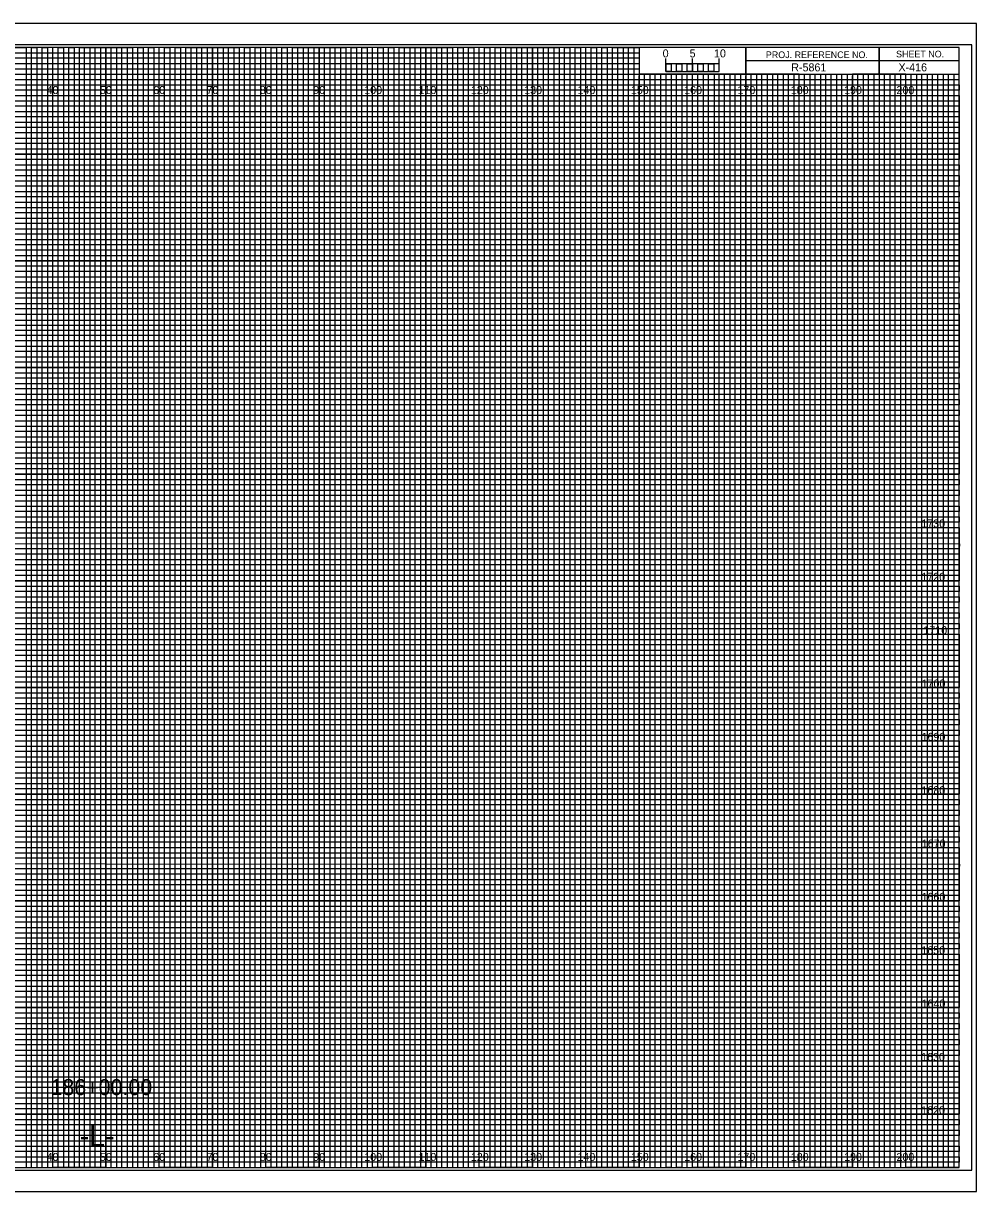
# Model space of a CAD drawing. Extents: x -13 to 323, y -5 to 6154.
# Drawn here: x 144.5 to 323.3, y 2635.5 to 2854.5 of the extents above; entities that cross this region are included whole.
import ezdxf

# ---------------------------------------------------------------- set-up
doc = ezdxf.new("R2010")
doc.units = 0
for name, color, linetype in [('Exist CMT Ground Line', 7, 'Continuous'), ('Prop Horizontal Alignment', 7, 'Continuous'), ('Prop Retaining Wall', 7, 'Continuous'), ('Prop XS Alignment Label', 7, 'Continuous'), ('Prop XS Bar Scale Labels', 7, 'Continuous'), ('Prop XS DDE', 7, 'Continuous'), ('Prop XS DDE Elevations', 7, 'Continuous'), ('Prop XS DDE Slope Text', 7, 'Continuous'), ('Prop XS Earthwork Shape', 7, 'Continuous'), ('Prop XS Elevation Labels', 7, 'Continuous'), ('Prop XS Project Number', 7, 'Continuous'), ('Prop XS Sheet Number', 7, 'Continuous'), ('Prop XS Station Labels', 7, 'Continuous'), ('Raster_Level_0', 7, 'Continuous'), ('Scratch_Level_3', 7, 'Continuous'), ('Sheet Cutting Line CELL', 7, 'Continuous')]:
    doc.layers.add(name, color=color, linetype=linetype)

msp = doc.modelspace()

# ---------------------------------------------------------------- linework, layer by layer
at = {"layer": 'Exist CMT Ground Line'}
for p, q in [((265, 2845.49), (265, 2847.9)), ((265, 2846.9), (265, 2847.9)), ((270, 2845.49), (270, 2847.9)), ((275, 2845.49), (275, 2847.9)), ((275, 2846.9), (275, 2847.9))]:
    msp.add_line(p, q, dxfattribs=at)
for points in [[(275, 2846.9), (265, 2846.9), (265, 2845.49), (275, 2845.49)], [(265, 2846.9), (266, 2846.9), (266, 2845.49), (265, 2845.49)], [(267, 2846.9), (268, 2846.9), (268, 2845.49), (267, 2845.49)], [(269, 2846.9), (270, 2846.9), (270, 2845.49), (269, 2845.49)], [(271, 2846.9), (272, 2846.9), (272, 2845.49), (271, 2845.49)], [(273, 2846.9), (274, 2846.9), (274, 2845.49), (273, 2845.49)]]:
    msp.add_lwpolyline(points, close=True, dxfattribs=at)
at = {"layer": 'Prop Retaining Wall'}
for p, q in [((0, 2849), (260, 2849)), ((260, 2847.98), (0, 2847.98)), ((0, 2847), (260, 2847)), ((260, 2849), (260, 2847.98)), ((260, 2847), (260, 2845.89)), ((260, 2845.89), (0, 2845.89)), ((0, 2844), (320, 2844))]:
    msp.add_line(p, q, dxfattribs=at)
for points in [[(0, 2843), (270, 2843), (320, 2843), (320, 2842), (0, 2842)], [(0, 2841), (320, 2841), (320, 2839), (0, 2839)], [(0, 2838), (320, 2838), (320, 2837), (0, 2836.98)], [(0, 2836), (320, 2836), (320, 2834), (0, 2834)], [(0, 2833), (320, 2833), (320, 2832), (0, 2832)], [(0, 2831), (320, 2831), (320, 2829), (0, 2829)], [(0, 2828), (320, 2828), (320, 2827), (0, 2827)], [(0, 2826), (320, 2826), (320, 2824), (0, 2824)], [(0, 2823), (320, 2823), (320, 2822), (0, 2822)], [(0, 2821), (320, 2821), (320, 2819), (0, 2819)], [(0, 2818), (320, 2818), (320, 2817), (0, 2817)], [(0, 2816), (320, 2816), (320, 2813.95), (320, 2813), (320, 2812), (0, 2812)], [(0, 2814), (320, 2814), (320, 2813), (0, 2813)], [(0, 2811), (320, 2811), (320, 2809), (0, 2809.03)], [(0, 2809.03), (320, 2809), (320, 2808), (0, 2808)], [(0, 2807), (320, 2807), (320, 2806), (0, 2806)], [(0, 2804), (320, 2804), (320, 2803), (0, 2803)], [(0, 2802), (320, 2802), (320, 2801), (0, 2801)], [(-0.07, 2798.89), (320, 2798.89), (320, 2797.88), (-0.07, 2797.88)], [(0, 2797), (320, 2797), (320, 2796), (0, 2796)], [(0, 2794), (320, 2794), (320, 2793), (0, 2793)], [(0, 2792), (320, 2792), (320, 2791), (0, 2791)], [(0, 2789), (320, 2789), (320, 2788), (0, 2788)], [(0, 2787), (320, 2787), (320, 2786), (0, 2786)], [(0, 2784), (320, 2784), (320, 2783), (0, 2783)], [(0, 2782), (320, 2782), (320, 2781), (0, 2781)], [(0, 2779), (320, 2779), (319.99, 2777.98), (0, 2778)], [(0, 2777), (320, 2777), (320, 2776), (0, 2776)], [(0, 2774), (320, 2774), (320, 2773), (0, 2773)], [(0, 2772), (320, 2772), (320, 2771), (0, 2771)], [(0, 2769), (320, 2769), (320, 2768), (0, 2768)], [(0, 2767), (320, 2767), (320, 2766), (0, 2766)], [(0, 2764), (320, 2764), (320, 2763), (0, 2763)], [(0, 2762), (320, 2762), (320, 2761), (0, 2761)], [(0, 2759), (320, 2759), (320, 2758), (0, 2758)], [(0, 2756.99), (320.07, 2756.91), (320, 2756), (0, 2756)], [(0, 2754), (320, 2754), (320, 2753), (0, 2753)], [(0, 2752), (320, 2752), (320, 2751), (0, 2751)], [(0, 2749), (320, 2749), (320, 2748), (0, 2748)], [(0, 2747), (320, 2747), (320, 2746), (0, 2746)], [(0, 2744), (320, 2744), (320, 2743), (0, 2743)], [(0, 2742), (320, 2742), (320, 2741), (0, 2741)], [(0, 2739), (320, 2739), (320, 2738), (0, 2738)], [(0, 2737), (320, 2737), (320, 2736), (0, 2736)], [(0, 2734), (320, 2734), (320, 2733), (0, 2733)], [(0, 2732), (320, 2732), (320, 2731), (0, 2731)], [(0, 2729), (320, 2729), (320, 2728), (0, 2728)], [(0, 2727), (320, 2727), (320, 2726), (0, 2726)], [(0, 2724), (320, 2724), (320, 2723), (0, 2723)], [(0, 2722), (320, 2722), (320, 2721), (0, 2721)], [(0, 2719), (320, 2719), (319.99, 2717.98), (0, 2718)], [(0, 2717), (320, 2717), (320, 2716), (0, 2716)], [(0, 2714), (320, 2714), (320, 2713), (0, 2713)], [(0, 2712), (320, 2712), (320, 2711), (0, 2711)], [(0, 2709), (320, 2709), (320, 2708), (0, 2708)], [(0, 2707), (320, 2707), (320, 2706), (0, 2706)], [(0, 2704), (320, 2704), (320, 2703), (0, 2703)], [(0, 2702), (320, 2702), (320, 2701), (0, 2701)], [(0, 2699), (320, 2699), (320, 2698), (0, 2698)], [(0, 2696.99), (320.07, 2696.91), (320, 2696), (0, 2696)], [(0, 2694), (320, 2694), (320, 2693), (0, 2693)], [(0, 2692), (320, 2692), (320, 2691), (0, 2691)], [(0, 2689), (320, 2689), (320, 2688), (0, 2688)], [(0, 2687), (320, 2687), (320, 2686), (0, 2686)], [(0, 2684), (320, 2684), (320, 2683), (0, 2683)], [(0, 2682), (320, 2682), (320, 2681), (0, 2681)], [(0, 2679), (320, 2679), (320, 2678), (0, 2678)], [(0, 2677), (320, 2677), (320, 2676), (0, 2676)], [(0, 2674), (320, 2674), (320, 2673), (0, 2673)], [(0, 2672), (320, 2672), (320, 2671), (0, 2671)], [(0, 2669), (320, 2669), (320, 2668), (0, 2668)], [(0, 2667), (320, 2667), (320, 2666), (0, 2666)], [(0, 2664), (320, 2664), (320, 2663), (0, 2663)], [(0, 2662), (320, 2662), (320, 2661), (0, 2661)], [(0, 2659), (320, 2659), (320, 2658), (0, 2658)], [(0, 2657), (320, 2657), (320, 2656), (0, 2656)], [(0, 2654), (320, 2654), (320, 2653), (0, 2653)], [(0, 2652), (320, 2652), (320, 2651), (0, 2651)], [(0, 2649), (320, 2649), (320, 2648), (0, 2648)], [(0, 2647), (320, 2647), (320, 2646), (0, 2646)], [(0, 2644), (320, 2644), (320, 2643), (0, 2643)], [(0, 2642), (320, 2642), (320, 2641), (0, 2641)]]:
    msp.add_lwpolyline(points, dxfattribs=at)
at = {"layer": 'Prop XS Alignment Label'}
for p, q in [((305, 2850), (305, 2845)), ((305, 2845), (305, 2850)), ((280, 2847.5), (280, 2845)), ((320, 2847.49), (280, 2847.49)), ((280, 2845), (320, 2845))]:
    msp.add_line(p, q, dxfattribs=at)
for points in [[(320, 2850), (0, 2850), (0, 2640), (320, 2640)], [(280, 2850), (260, 2850), (260, 2845.03), (280, 2845.03)], [(320, 2850), (280, 2850), (280, 2845), (320, 2845)]]:
    msp.add_lwpolyline(points, close=True, dxfattribs=at)
at = {"layer": 'Prop XS DDE'}
msp.add_lwpolyline([(-13.4, 2635.5), (323.3, 2635.5), (323.3, 2854.5), (-13.4, 2854.5)], close=True, dxfattribs=at)
at = {"layer": 'Prop XS DDE Elevations'}
for p, q in [((150, 2640), (150, 2850)), ((160, 2640), (160, 2850)), ((170, 2640), (170, 2850)), ((180, 2640), (180, 2850)), ((190, 2640), (190, 2850)), ((200, 2640), (200, 2850)), ((210, 2640), (210, 2850)), ((220, 2640), (220, 2850)), ((230, 2640), (230, 2850)), ((240, 2640), (240, 2850)), ((250, 2640), (250, 2850)), ((260, 2640), (260, 2844.69)), ((270, 2640), (270, 2844.69)), ((280, 2640), (280, 2844.69)), ((290, 2640), (290, 2844.69)), ((300, 2640), (300, 2844.69)), ((310, 2640), (310, 2844.69)), ((0, 2840), (320, 2840)), ((0, 2830), (320, 2830)), ((0, 2820), (320, 2820)), ((0, 2810), (320, 2810)), ((0, 2800), (320, 2800)), ((0, 2790), (320, 2790)), ((0, 2780), (320, 2780)), ((0, 2770), (320, 2770)), ((0, 2760), (320, 2760)), ((0, 2750), (320, 2750)), ((0, 2740), (320, 2740)), ((0, 2730), (320, 2730)), ((0, 2720), (320, 2720)), ((0, 2710), (320, 2710)), ((0, 2700), (320, 2700)), ((0, 2690), (320, 2690)), ((0, 2680), (320, 2680)), ((0, 2670), (320, 2670)), ((0, 2660), (320, 2660)), ((0, 2650), (320, 2650))]:
    msp.add_line(p, q, dxfattribs=at)
at = {"layer": 'Prop XS DDE Slope Text'}
msp.add_lwpolyline([(-10.8, 2639.5), (322.4, 2639.5), (322.4, 2850.5), (-10.8, 2850.5)], close=True, dxfattribs=at)
at = {"layer": 'Prop XS Earthwork Shape'}
for p, q in [((150, 2850), (140, 2850)), ((150, 2640), (150, 2850)), ((170, 2850), (160, 2850)), ((160, 2850), (160, 2640)), ((170, 2640), (170, 2850)), ((190, 2850), (180, 2850)), ((180, 2850), (180, 2640)), ((190, 2640), (190, 2850)), ((210, 2850), (200, 2850)), ((200, 2850), (200, 2640)), ((210, 2640), (210, 2850)), ((230, 2850), (220, 2850)), ((220, 2850), (220, 2640)), ((230, 2640), (230, 2850)), ((250, 2850), (240, 2850)), ((240, 2850), (240, 2640)), ((250, 2640), (250, 2850)), ((260, 2850), (260, 2640)), ((270, 2640), (270, 2845)), ((290, 2845), (280, 2845)), ((280, 2845), (280, 2640)), ((290, 2640), (290, 2845)), ((310, 2845), (300, 2845)), ((300, 2845), (300, 2640)), ((310, 2640), (310, 2845)), ((160, 2640), (150, 2640)), ((180, 2640), (170, 2640)), ((200, 2640), (190, 2640)), ((220, 2640), (210, 2640)), ((240, 2640), (230, 2640)), ((260, 2640), (250, 2640)), ((280, 2640), (270, 2640)), ((300, 2640), (290, 2640)), ((320, 2640), (310, 2640)), ((320, 2640), (320, 2640))]:
    msp.add_line(p, q, dxfattribs=at)
for points in [[(0, 2840), (320, 2840), (320, 2830), (0, 2830)], [(0, 2820), (320, 2820), (320, 2810), (0, 2810)], [(0, 2800), (320, 2800), (320, 2790), (0, 2790)], [(0, 2780), (320, 2780), (320, 2770), (0, 2770)], [(0, 2760), (320, 2760), (320, 2750), (0, 2750)], [(0, 2740), (320, 2740), (320, 2730), (0, 2730)], [(0, 2720), (320, 2720), (320, 2710), (0, 2710)], [(0, 2700), (320, 2700), (320, 2690), (0, 2690)], [(0, 2680), (320, 2680), (320, 2670), (0, 2670)], [(0, 2660), (320, 2660), (320, 2650), (0, 2650)]]:
    msp.add_lwpolyline(points, dxfattribs=at)
at = {"layer": 'Prop XS Elevation Labels'}
for p, q in [((267, 2845), (266.01, 2845)), ((266.01, 2845), (266.01, 2640)), ((267, 2640), (267, 2845)), ((269, 2845), (268, 2845)), ((268, 2845), (268, 2640)), ((269, 2640), (269, 2845)), ((266.01, 2640), (265, 2640)), ((268, 2640), (267, 2640))]:
    msp.add_line(p, q, dxfattribs=at)
for points in [[(145, 2640), (146, 2640), (146, 2850), (147, 2850), (147, 2640)], [(147, 2640), (148, 2640), (148, 2850), (149, 2850), (149, 2640)], [(150, 2640), (151, 2640), (151, 2850), (152, 2850), (152, 2640)], [(152, 2640), (153, 2640), (153, 2850), (154, 2850), (154, 2640)], [(155, 2640), (156, 2640), (156, 2850), (157, 2850), (157, 2640)], [(157, 2640), (158, 2640), (158, 2850), (159, 2850), (159, 2640)], [(160, 2640), (161, 2640), (161, 2850), (162, 2850), (162, 2640)], [(162, 2640), (163, 2640), (163, 2850), (164, 2850), (164, 2640)], [(165, 2640), (166, 2640), (166, 2850), (167, 2850), (167, 2640)], [(167, 2640), (168, 2640), (168, 2850), (169, 2850), (169, 2640)], [(170, 2640), (171, 2640), (171, 2850), (172, 2850), (172, 2640)], [(172, 2640), (173, 2640), (173, 2850), (174, 2850), (174, 2640)], [(175, 2640), (176, 2640), (176, 2850), (177, 2850), (177, 2640)], [(177, 2640), (178, 2640), (178, 2850), (179, 2850), (179, 2640)], [(180, 2640), (181, 2640), (181, 2850), (182, 2850), (182, 2640)], [(182, 2640), (183, 2640), (183, 2850), (184, 2850), (184, 2640)], [(185, 2640), (186, 2640), (186, 2850), (187, 2850), (187, 2640)], [(187, 2640), (188, 2640), (188, 2850), (189, 2850), (189, 2640)], [(190, 2640), (191, 2640), (191, 2850), (192, 2850), (192, 2640)], [(192, 2640), (193, 2640), (193, 2850), (194, 2850), (194, 2640)], [(195, 2640), (196, 2640), (196, 2850), (197, 2850), (197, 2640)], [(197, 2640), (198, 2640), (198, 2850), (199, 2850), (199, 2640)], [(200, 2640), (201, 2640), (201, 2850), (202, 2850), (202, 2640)], [(202, 2640), (203, 2640), (203, 2850), (204, 2850), (204, 2640)], [(205, 2640), (206, 2640), (206, 2850), (207, 2850), (207, 2640)], [(207, 2640), (208, 2640), (208, 2850), (209, 2850), (209, 2640)], [(210, 2640), (211, 2640), (211, 2850), (212, 2850), (212, 2640)], [(212, 2640), (213, 2640), (213, 2850), (214, 2850), (214, 2640)], [(215, 2640), (216, 2640), (216, 2850), (217, 2850), (217, 2640)], [(217, 2640), (218, 2640), (218, 2850), (219, 2850), (219, 2640)], [(220, 2640), (221, 2640), (221, 2850), (222, 2850), (222, 2640)], [(222, 2640), (223, 2640), (223, 2850), (224, 2850), (224, 2640)], [(225, 2640), (226, 2640), (226, 2850), (227, 2850), (227, 2640)], [(227, 2640), (228, 2640), (228, 2850), (229, 2850), (229, 2640)], [(230, 2640), (231, 2640), (231, 2850), (232, 2850), (232, 2640)], [(232, 2640), (233, 2640), (233, 2850), (234, 2850), (234, 2640)], [(235, 2640), (236, 2640), (236, 2850), (237, 2850), (237, 2640)], [(237, 2640), (238, 2640), (238, 2850), (239, 2850), (239, 2640)], [(240, 2640), (241, 2640), (241, 2850), (242, 2850), (242, 2640)], [(242, 2640), (243, 2640), (243, 2850), (244, 2850), (244, 2640)], [(245, 2640), (246, 2640), (246, 2850), (247, 2850), (247, 2640)], [(247, 2640), (248, 2640), (248, 2850), (249, 2850), (249, 2640)], [(250, 2640), (251, 2640), (251, 2850), (252, 2850), (252, 2640)], [(252, 2640), (253, 2640), (253, 2850), (254, 2850), (254, 2640)], [(255, 2640), (256, 2640), (256, 2850), (257, 2850), (257, 2640)], [(257, 2640), (258, 2640), (258, 2850), (259, 2850), (259, 2640)], [(260, 2640), (261, 2640), (261, 2845), (262.02, 2845), (262.02, 2640)], [(262, 2640), (263, 2640), (263, 2845), (263.99, 2845), (263.99, 2640)], [(270, 2640), (270.98, 2640), (270.98, 2845), (272, 2845), (272, 2640)], [(272, 2640), (273, 2640), (273, 2845), (274.05, 2845), (274.05, 2640)], [(275, 2640), (276, 2640), (276, 2845), (277, 2845), (277, 2640)], [(277, 2640), (278, 2640), (278, 2845), (279, 2845), (279, 2640)], [(280, 2640), (281, 2640), (281, 2845), (282, 2845), (282, 2640)], [(282, 2640), (283, 2640), (283, 2845), (284, 2845), (284, 2640)], [(285, 2640), (286, 2640), (286, 2845), (287, 2845), (287, 2640)], [(287, 2640), (288, 2640), (288, 2845), (289, 2845), (289, 2640)], [(290, 2640), (291, 2640), (291, 2845), (292, 2845), (292, 2640)], [(292, 2640), (293, 2640), (293, 2845), (294, 2845), (294, 2640)], [(295, 2640), (296, 2640), (296, 2845), (297, 2845), (297, 2640)], [(297, 2640), (298, 2640), (298, 2845), (299, 2845), (299, 2640)], [(300, 2640), (301, 2640), (301, 2845), (302, 2845), (302, 2640)], [(302, 2640), (303, 2640), (303, 2845), (304, 2845), (304, 2640)], [(305, 2640), (306, 2640), (306, 2845), (307, 2845), (307, 2640)], [(307, 2640), (308, 2640), (308, 2845), (309, 2845), (309, 2640)], [(310, 2640), (311, 2640), (311, 2845), (312, 2845), (312, 2640)], [(312, 2640), (313, 2640), (313, 2845), (314, 2845), (314, 2640)], [(315, 2640), (316, 2640), (316, 2845), (317, 2845), (317, 2640)], [(317, 2640), (318, 2640), (318, 2845), (319, 2845), (319, 2640)]]:
    msp.add_lwpolyline(points, dxfattribs=at)
at = {"layer": 'Prop XS Station Labels'}
for points in [[(135, 2850), (145, 2850), (145, 2640), (155, 2640), (155, 2850), (165, 2850), (165, 2640), (175, 2640), (175, 2850), (185, 2850), (185, 2640), (195, 2640), (195, 2850), (205, 2850), (205, 2640), (215, 2640), (215, 2850), (225, 2850), (225, 2640), (235, 2640), (235, 2850), (245, 2850), (245, 2640), (255, 2640), (255, 2850), (259.93, 2850), (260, 2850), (260, 2845), (264.99, 2845), (264.99, 2640), (275, 2640), (275, 2845), (285, 2845), (285, 2640), (295, 2640), (295, 2845), (305, 2845), (305, 2640), (315, 2640), (315, 2845)], [(0, 2845), (275, 2845)], [(0, 2825), (320, 2825), (320, 2835), (0, 2835)], [(0, 2805), (320, 2805), (320, 2815), (0, 2815)], [(0, 2785), (320, 2785), (320, 2795), (0, 2795)], [(0, 2765), (320, 2765), (320, 2775), (0, 2775)], [(0, 2745), (320, 2745), (320, 2755), (0, 2755)], [(0, 2725), (320, 2725), (320, 2735), (0, 2735)], [(0, 2705), (320, 2705), (320, 2715), (0, 2715)], [(0, 2685), (320, 2685), (320, 2695), (0, 2695)], [(0, 2665), (320, 2665), (320, 2675), (0, 2675)], [(0, 2645), (320, 2645), (320, 2655), (0, 2655)]]:
    msp.add_lwpolyline(points, dxfattribs=at)
at = {"layer": 'Sheet Cutting Line CELL'}
for p, q in [((323.3, 2854.5), (-13.4, 2854.5)), ((-13.4, 2635.5), (323.3, 2635.5))]:
    msp.add_line(p, q, dxfattribs=at)

# ---------------------------------------------------------------- texts
at = {"layer": 'Exist CMT Ground Line'}
msp.add_text('0', height=1.5, dxfattribs=at).set_placement((264.41, 2848.12))
at = {"layer": 'Prop Horizontal Alignment'}
msp.add_text('186+00.00', height=3, dxfattribs=at).set_placement((149.59, 2653.59))
at = {"layer": 'Prop XS Alignment Label'}
for s, height, p in [('PROJ. REFERENCE NO.', 1.25, (283.77, 2847.99)), ('SHEET NO.', 1.25, (308.19, 2848.12)), ('-L-', 4, (155.06, 2644))]:
    msp.add_text(s, height=height, dxfattribs=at).set_placement(p)
at = {"layer": 'Prop XS Bar Scale Labels'}
for s, p in [('5', (269.47, 2848.12)), ('10', (274.04, 2848.12))]:
    msp.add_text(s, height=1.5, dxfattribs=at).set_placement(p)
at = {"layer": 'Prop XS Project Number'}
msp.add_text('R-5861', height=1.5, dxfattribs=at).set_placement((288.53, 2845.5))
at = {"layer": 'Prop XS Sheet Number'}
msp.add_text('X-416', height=1.5, dxfattribs=at).set_placement((308.64, 2845.51))
at = {"layer": 'Raster_Level_0'}
for s, p in [('40', (148.86, 2841.25)), ('50', (158.86, 2841.25)), ('60', (168.86, 2841.25)), ('70', (178.86, 2841.25)), ('80', (188.86, 2841.25)), ('90', (198.86, 2841.25)), ('100', (208.44, 2841.25)), ('110', (218.62, 2841.25)), ('120', (228.44, 2841.25)), ('130', (238.44, 2841.25)), ('140', (248.44, 2841.25)), ('150', (258.44, 2841.25)), ('160', (268.44, 2841.25)), ('170', (278.44, 2841.25)), ('180', (288.44, 2841.25)), ('190', (298.44, 2841.25)), ('200', (308.26, 2841.25)), ('40', (148.86, 2641.25)), ('50', (158.86, 2641.25)), ('60', (168.86, 2641.25)), ('70', (178.86, 2641.25)), ('80', (188.86, 2641.25)), ('90', (198.86, 2641.25)), ('100', (208.44, 2641.25)), ('110', (218.62, 2641.25)), ('120', (228.44, 2641.25)), ('130', (238.44, 2641.25)), ('140', (248.44, 2641.25)), ('150', (258.44, 2641.25)), ('160', (268.44, 2641.25)), ('170', (278.44, 2641.25)), ('180', (288.44, 2641.25)), ('190', (298.44, 2641.25)), ('200', (308.26, 2641.25))]:
    msp.add_text(s, height=1.5, dxfattribs=at).set_placement(p)
at = {"layer": 'Scratch_Level_3'}
for s, p in [('1730', (312.92, 2760)), ('1720', (312.93, 2750)), ('1710', (313.31, 2740)), ('1700', (312.98, 2730)), ('1690', (312.97, 2720)), ('1680', (312.95, 2710)), ('1670', (313, 2700)), ('1660', (312.97, 2690)), ('1650', (312.92, 2680)), ('1640', (312.97, 2670)), ('1630', (312.89, 2660)), ('1620', (312.9, 2650))]:
    msp.add_text(s, height=1.5, dxfattribs=at).set_placement(p)

doc.saveas('drawing.dxf')
